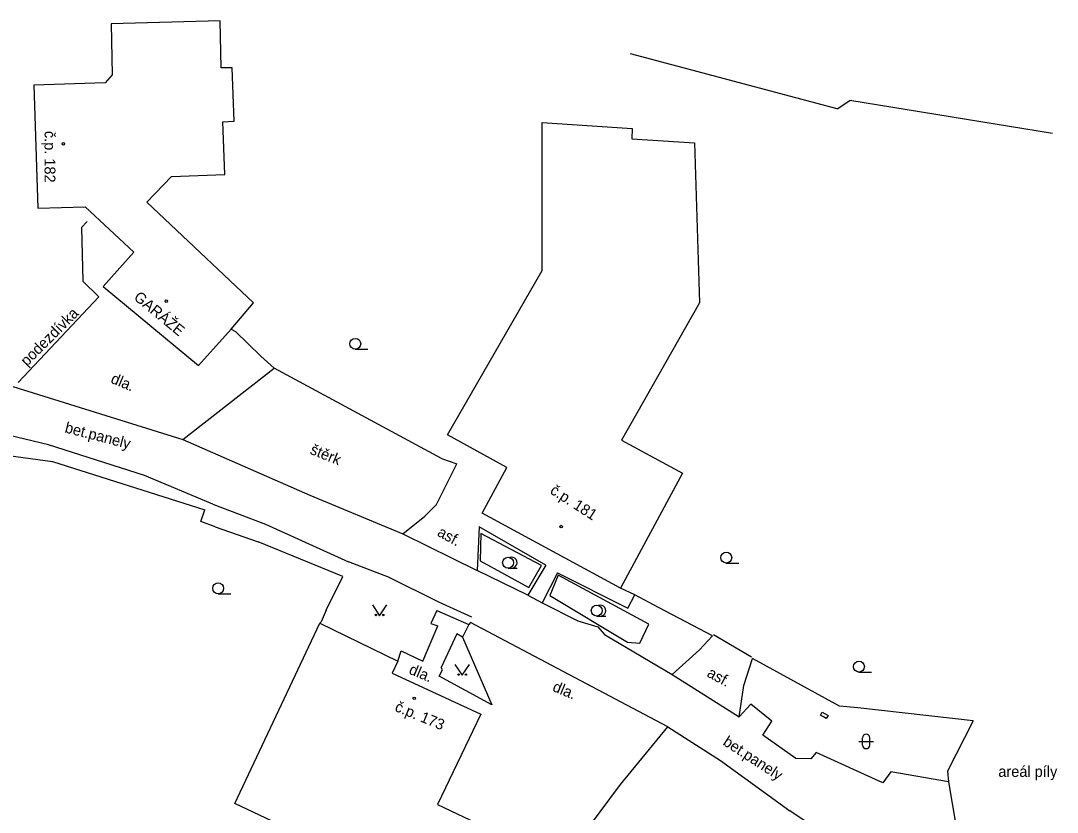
# Model space of a CAD drawing. Extents: x -544674 to -541478, y -1199076 to -1195527.
# Drawn here: x -543619.7 to -543548.2, y -1196931.8 to -1196877.2 of the extents above; entities that cross this region are included whole.
import ezdxf

# ---------------------------------------------------------------- set-up
doc = ezdxf.new("R2010")
doc.units = 0
for name, color, linetype in [('BUDOVY_MĚŘ', 7, 'Continuous'), ('BUDOVY_NEMĚŘ', 7, 'Continuous'), ('OBVOD_PILÍŘE', 7, 'Continuous'), ('POMOC_POPIS', 7, 'Continuous'), ('ROZHRANÍ_PLOCH', 7, 'Continuous'), ('ZELEŇ', 7, 'Continuous'), ('ZN_BUDOV', 7, 'Continuous'), ('ZN_DOPLŇKOVÉ', 7, 'Continuous'), ('ZN_KULTUR', 7, 'Continuous'), ('Č_POPIS_ORIENT', 7, 'Continuous')]:
    doc.layers.add(name, color=color, linetype=linetype)

msp = doc.modelspace()

# ---------------------------------------------------------------- linework, layer by layer
at = {"layer": 'BUDOVY_MĚŘ'}
for points in [[(-543613.99, -1196895.51), (-543607.41, -1196900.97)], [(-543605.17, -1196898.46), (-543607.41, -1196900.97)], [(-543586.14, -1196908), (-543590.24, -1196905.76)], [(-543587.85, -1196911.15), (-543586.14, -1196908)], [(-543578.31, -1196916.34), (-543587.85, -1196911.15)], [(-543599.04, -1196918.74), (-543593.66, -1196921.36)], [(-543593.66, -1196921.36), (-543594.06, -1196922.2)], [(-543594.06, -1196922.2), (-543587.93, -1196925.02), (-543590.93, -1196931.25), (-543584.67, -1196934.23), (-543585.35, -1196936.49)]]:
    msp.add_lwpolyline(points, dxfattribs=at)
at = {"layer": 'BUDOVY_NEMĚŘ'}
for points in [[(-543605.93, -1196877.18), (-543613.44, -1196877.4)], [(-543613.44, -1196877.4), (-543613.37, -1196880.92)], [(-543605.86, -1196880.44), (-543605.93, -1196877.18)], [(-543605.09, -1196880.42), (-543605.86, -1196880.44)], [(-543604.96, -1196884.12), (-543605.09, -1196880.42)], [(-543613.37, -1196880.92), (-543613.86, -1196881.46)], [(-543613.86, -1196881.46), (-543618.79, -1196881.63)], [(-543618.79, -1196881.63), (-543618.51, -1196890.12)], [(-543605.73, -1196884.15), (-543604.96, -1196884.12)], [(-543605.61, -1196887.8), (-543605.73, -1196884.15)], [(-543583.71, -1196894.42), (-543583.7, -1196884.2)], [(-543583.7, -1196884.2), (-543577.49, -1196884.62)], [(-543577.49, -1196884.62), (-543577.52, -1196885.32)], [(-543577.52, -1196885.32), (-543573.2, -1196885.61)], [(-543573.2, -1196885.61), (-543572.85, -1196896.64)], [(-543610.99, -1196889.7), (-543609.28, -1196887.93)], [(-543609.28, -1196887.93), (-543605.61, -1196887.8)], [(-543603.62, -1196896.64), (-543610.99, -1196889.7)], [(-543618.51, -1196890.12), (-543615.23, -1196890.03)], [(-543615.23, -1196890.03), (-543611.89, -1196893.15)], [(-543611.89, -1196893.15), (-543613.99, -1196895.51)], [(-543590.24, -1196905.76), (-543583.71, -1196894.42)], [(-543605.17, -1196898.46), (-543603.62, -1196896.64)], [(-543572.85, -1196896.64), (-543577.69, -1196905.16)], [(-543577.69, -1196905.16), (-543578.24, -1196906.12)], [(-543578.24, -1196906.12), (-543574.03, -1196908.4)], [(-543574.03, -1196908.4), (-543578.31, -1196916.34)], [(-543604.91, -1196931.19), (-543599.04, -1196918.74)], [(-543593.88, -1196936.4), (-543604.91, -1196931.19)]]:
    msp.add_lwpolyline(points, dxfattribs=at)
at = {"layer": 'OBVOD_PILÍŘE'}
msp.add_lwpolyline([(-543564.3, -1196925.21), (-543564.5, -1196925.09), (-543564.38, -1196924.88), (-543563.97, -1196925.11), (-543564.1, -1196925.33), (-543564.3, -1196925.21)], dxfattribs=at)
at = {"layer": 'ROZHRANÍ_PLOCH'}
for points in [[(-543615.09, -1196891.04), (-543615.48, -1196891.45)], [(-543615.48, -1196891.45), (-543615.41, -1196895.14)], [(-543615.41, -1196895.14), (-543614.29, -1196896.24)], [(-543608.5, -1196906.08), (-543602.2, -1196901.15)], [(-543620.22, -1196902.42), (-543608.5, -1196906.08)], [(-543617.76, -1196906.45), (-543622.69, -1196905.26)], [(-543608.5, -1196906.08), (-543599.74, -1196909.91)], [(-543611.14, -1196908.55), (-543617.76, -1196906.45)], [(-543590.66, -1196907.38), (-543589.59, -1196907.75)], [(-543591, -1196910.56), (-543589.59, -1196907.75)], [(-543606.43, -1196910.53), (-543611.14, -1196908.55)], [(-543599.74, -1196909.91), (-543593.32, -1196912.57)], [(-543606.43, -1196910.53), (-543602.79, -1196911.92)], [(-543591.8, -1196911.37), (-543591, -1196910.56)], [(-543593.32, -1196912.57), (-543591.8, -1196911.37)], [(-543602.79, -1196911.92), (-543597.07, -1196914.52)], [(-543593.32, -1196912.57), (-543588.18, -1196915.1)], [(-543588.05, -1196912.09), (-543588.18, -1196915.1)], [(-543583.46, -1196914.74), (-543588.05, -1196912.09)], [(-543594.31, -1196915.57), (-543597.07, -1196914.52)], [(-543583.46, -1196914.74), (-543584.69, -1196916.82)], [(-543584.69, -1196916.82), (-543588.18, -1196915.1)], [(-543582.65, -1196915.27), (-543583.7, -1196917.35)], [(-543582.65, -1196915.27), (-543577.79, -1196917.72)], [(-543590.83, -1196917.29), (-543594.31, -1196915.57)], [(-543584.69, -1196916.82), (-543583.7, -1196917.35)], [(-543577.79, -1196917.72), (-543577.32, -1196916.79)], [(-543588.55, -1196918.33), (-543590.83, -1196917.29)], [(-543583.7, -1196917.35), (-543581.25, -1196918.59)], [(-543590.98, -1196917.86), (-543591.39, -1196918.77)], [(-543590.98, -1196917.86), (-543588.76, -1196918.83)], [(-543591.93, -1196921.37), (-543590.91, -1196918.92)], [(-543591.39, -1196918.77), (-543590.91, -1196918.92)], [(-543588.76, -1196918.83), (-543589.2, -1196919.72)], [(-543588.65, -1196918.69), (-543588.76, -1196918.83)], [(-543575.04, -1196925.9), (-543588.65, -1196918.69)], [(-543581.25, -1196918.59), (-543579.87, -1196918.99)], [(-543579.87, -1196918.99), (-543579.4, -1196919.53)], [(-543589.59, -1196919.49), (-543590.67, -1196921.8)], [(-543589.2, -1196919.72), (-543589.59, -1196919.49)], [(-543589.2, -1196919.72), (-543587.18, -1196924.37)], [(-543579.4, -1196919.53), (-543574.73, -1196922.28)], [(-543571.95, -1196919.61), (-543572.85, -1196920.58)], [(-543593.66, -1196921.36), (-543593.43, -1196920.65)], [(-543593.43, -1196920.65), (-543591.93, -1196921.37)], [(-543572.85, -1196920.58), (-543574.73, -1196922.28)], [(-543569.78, -1196923.04), (-543569.19, -1196921.19)], [(-543590.59, -1196921.96), (-543590.67, -1196921.8)], [(-543590.82, -1196922.39), (-543590.59, -1196921.96)], [(-543587.18, -1196924.37), (-543590.82, -1196922.39)], [(-543574.73, -1196922.28), (-543570.12, -1196925.21)], [(-543570.12, -1196925.21), (-543569.78, -1196923.04)], [(-543569.31, -1196924.33), (-543570.12, -1196925.21)], [(-543567.86, -1196925.5), (-543569.31, -1196924.33)], [(-543578.3, -1196929.87), (-543575.04, -1196925.9)], [(-543575.04, -1196925.9), (-543571.39, -1196928.21)], [(-543568.48, -1196926.46), (-543567.86, -1196925.5)], [(-543566.2, -1196928.08), (-543568.48, -1196926.46)], [(-543571.39, -1196928.21), (-543566.61, -1196931.69)], [(-543565.16, -1196928.1), (-543566.2, -1196928.08)], [(-543564.81, -1196927.66), (-543565.16, -1196928.1)], [(-543560.19, -1196929.76), (-543564.81, -1196927.66)], [(-543559.65, -1196929.01), (-543560.19, -1196929.76)], [(-543555.66, -1196929.7), (-543559.65, -1196929.01)], [(-543580.45, -1196932.76), (-543578.3, -1196929.87)], [(-543560.69, -1196935.66), (-543566.61, -1196931.69)]]:
    msp.add_lwpolyline(points, dxfattribs=at)
at = {"layer": 'ZELEŇ'}
for points in [[(-543587.94, -1196912.56), (-543587.99, -1196914.45)], [(-543583.76, -1196914.76), (-543587.94, -1196912.56)], [(-543587.99, -1196914.45), (-543584.62, -1196916.28)], [(-543584.62, -1196916.28), (-543583.76, -1196914.76)], [(-543582.59, -1196915.43), (-543583.18, -1196916.84)], [(-543576.35, -1196918.82), (-543582.59, -1196915.43)], [(-543583.18, -1196916.84), (-543577.82, -1196920.05)], [(-543576.96, -1196920.12), (-543576.35, -1196918.82)], [(-543577.82, -1196920.05), (-543576.96, -1196920.12)]]:
    msp.add_lwpolyline(points, dxfattribs=at)
at = {"layer": 'ZN_BUDOV'}
for centre in [(-543616.74, -1196885.67), (-543609.64, -1196896.53), (-543582.39, -1196912.08), (-543592.53, -1196923.93)]:
    msp.add_circle(centre, 0.0875, dxfattribs=at)
at = {"layer": 'ZN_DOPLŇKOVÉ'}
for points in [[(-543563.36, -1196883.26), (-543577.62, -1196879.47)], [(-543563.36, -1196883.26), (-543562.48, -1196882.69)], [(-543548.49, -1196884.97), (-543562.48, -1196882.69)], [(-543614.29, -1196896.24), (-543619.87, -1196902.14)], [(-543605.17, -1196898.46), (-543604.86, -1196898.62)], [(-543604.86, -1196898.62), (-543603.12, -1196900.33)], [(-543603.12, -1196900.33), (-543602.2, -1196901.15)], [(-543590.66, -1196907.38), (-543602.2, -1196901.15)], [(-543622.57, -1196906.89), (-543617.49, -1196907.59)], [(-543617.49, -1196907.59), (-543606.99, -1196910.92)], [(-543607.25, -1196911.73), (-543606.99, -1196910.92)], [(-543606.26, -1196912.1), (-543607.25, -1196911.73)], [(-543606.26, -1196912.1), (-543603.3, -1196913.14)], [(-543597.45, -1196915.52), (-543603.3, -1196913.14)], [(-543598.62, -1196917.84), (-543597.45, -1196915.52)], [(-543571.95, -1196919.61), (-543575.68, -1196917.66), (-543577.32, -1196916.79), (-543578.31, -1196916.34)], [(-543598.62, -1196917.84), (-543598.95, -1196918.65)], [(-543599.04, -1196918.74), (-543598.95, -1196918.65)], [(-543569.27, -1196921.1), (-543571.89, -1196919.55)], [(-543563.2, -1196924.46), (-543569.19, -1196921.19)], [(-543561.92, -1196924.59), (-543563.2, -1196924.46)], [(-543553.97, -1196925.49), (-543561.92, -1196924.59)], [(-543553.97, -1196925.49), (-543555.74, -1196928.95)], [(-543555.74, -1196928.95), (-543555.66, -1196929.7)], [(-543555.66, -1196929.7), (-543554.93, -1196934.03)]]:
    msp.add_lwpolyline(points, dxfattribs=at)
at = {"layer": 'ZN_KULTUR'}
for p, q in [((-543596.6, -1196899.845), (-543595.725, -1196899.845)), ((-543571, -1196914.595), (-543570.125, -1196914.595)), ((-543586.06, -1196914.945), (-543585.435, -1196914.945)), ((-543606.06, -1196916.715), (-543605.185, -1196916.715)), ((-543579.94, -1196918.255), (-543579.315, -1196918.255)), ((-543561.85, -1196922.115), (-543560.975, -1196922.115)), ((-543561.85, -1196926.9), (-543560.85, -1196926.9)), ((-543561.6, -1196927.15), (-543561.6, -1196926.65)), ((-543561.1, -1196927.15), (-543561.1, -1196926.65))]:
    msp.add_line(p, q, dxfattribs=at)
for points in [[(-543595.42, -1196917.48), (-543594.92, -1196918.23), (-543594.42, -1196917.48)], [(-543589.72, -1196921.59), (-543589.22, -1196922.34), (-543588.72, -1196921.59)]]:
    msp.add_lwpolyline(points, dxfattribs=at)
for centre, radius in [((-543596.6, -1196899.47), 0.375), ((-543571, -1196914.22), 0.375), ((-543586.06, -1196914.57), 0.375), ((-543606.06, -1196916.34), 0.375), ((-543579.94, -1196917.88), 0.375), ((-543595.17, -1196918.18), 0.05), ((-543594.67, -1196918.18), 0.05), ((-543561.85, -1196921.74), 0.375), ((-543589.47, -1196922.29), 0.05), ((-543588.97, -1196922.29), 0.05)]:
    msp.add_circle(centre, radius, dxfattribs=at)
for centre, radius, start, end in [((-543585.81, -1196914.57), 0.375, 249.49437, 109.04743), ((-543579.69, -1196917.88), 0.375, 249.49437, 109.04743), ((-543561.35, -1196926.65), 0.25, 0, 179.99999), ((-543561.35, -1196927.15), 0.25, 179.99999, 359.99999)]:
    msp.add_arc(centre, radius, start, end, dxfattribs=at)

# ---------------------------------------------------------------- texts
at = {"layer": 'POMOC_POPIS'}
for s, rotation, p in [('GARÁŽE', 320.38998, (-543611.94, -1196896.36)), ('podezdívka', 44.99999, (-543619.26, -1196901.06)), ('dla.', 337.30002, (-543613.53, -1196902.14)), ('bet.panely', 345.34, (-543616.69, -1196905.57)), ('štěrk', 337.83998, (-543599.78, -1196907.04)), ('asf.', 331.21, (-543591, -1196912.68)), ('dla.', 337.30002, (-543592.96, -1196922.21)), ('asf.', 331.21, (-543572.39, -1196922.39)), ('dla.', 337.30002, (-543583.05, -1196923.4)), ('bet.panely', 326.95, (-543571.29, -1196927.1))]:
    msp.add_text(s, height=0.75, rotation=rotation, dxfattribs=at).set_placement(p)
msp.add_text('areál píly', height=0.75, dxfattribs=at).set_placement((-543552.23, -1196929.35))
at = {"layer": 'Č_POPIS_ORIENT'}
for s, rotation, p in [('č.p. 182', 270, (-543618.04, -1196884.78)), ('č.p. 181', 327.21998, (-543583.22, -1196909.75)), ('č.p. 173', 337.42997, (-543593.93, -1196924.78))]:
    msp.add_text(s, height=0.75, rotation=rotation, dxfattribs=at).set_placement(p)

doc.saveas('drawing.dxf')
